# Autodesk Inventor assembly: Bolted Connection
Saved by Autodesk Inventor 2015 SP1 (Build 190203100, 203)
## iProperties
Category: Mechanical Engineering Drawing and Design - CADD
Manager: Fábio Ricardo de Oliveira Souza
Company: SENAI - Serviço Nacional de Aprendizagem Industrial
Created: 2011-06
Part Number: Bolted Connection
Document SubType Name: Assembly
Designer: Guilherme Augusto Franco de Souza
Engineer: George Geraldo de Oliveia Silva
Authority: Fábio Ricardo de Oliveira Soza
Description: Purchased
Subject: WorldSkill 2011 - London, England
Author: Guilherme Augusto Franco de Souza
Revision Number: 00
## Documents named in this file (4)
- E:\Visitor Experience Project\WSI2015 - Visitor Experience Project\#46- Sheet Metal Technology\01- 3D Models\Outodoor Heater\2- Assemblies\Bolted Connection.iam
- C:\Users\SENAI\Desktop\WorldSkill 2011\Content Center\en-US\ISO 4017(1)\ISO 4017 - M6 x 16ISO.ipt
- C:\Users\SENAI\Desktop\WorldSkill 2011\Content Center\en-US\ISO 7089\ISO 7089 - 6 - 140 HV(1).ipt
- C:\Users\SENAI\Desktop\WorldSkill 2011\Content Center\en-US\ISO 4032(2)\ISO 4032 - M6ISO.ipt
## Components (4 placed, 3 different names)
1. ISO 4017 M6 x 16:1
2. ISO 7089 6 - 140 HV:1
3. ISO 7089 6 - 140 HV:2
4. ISO 4032 M6:1
